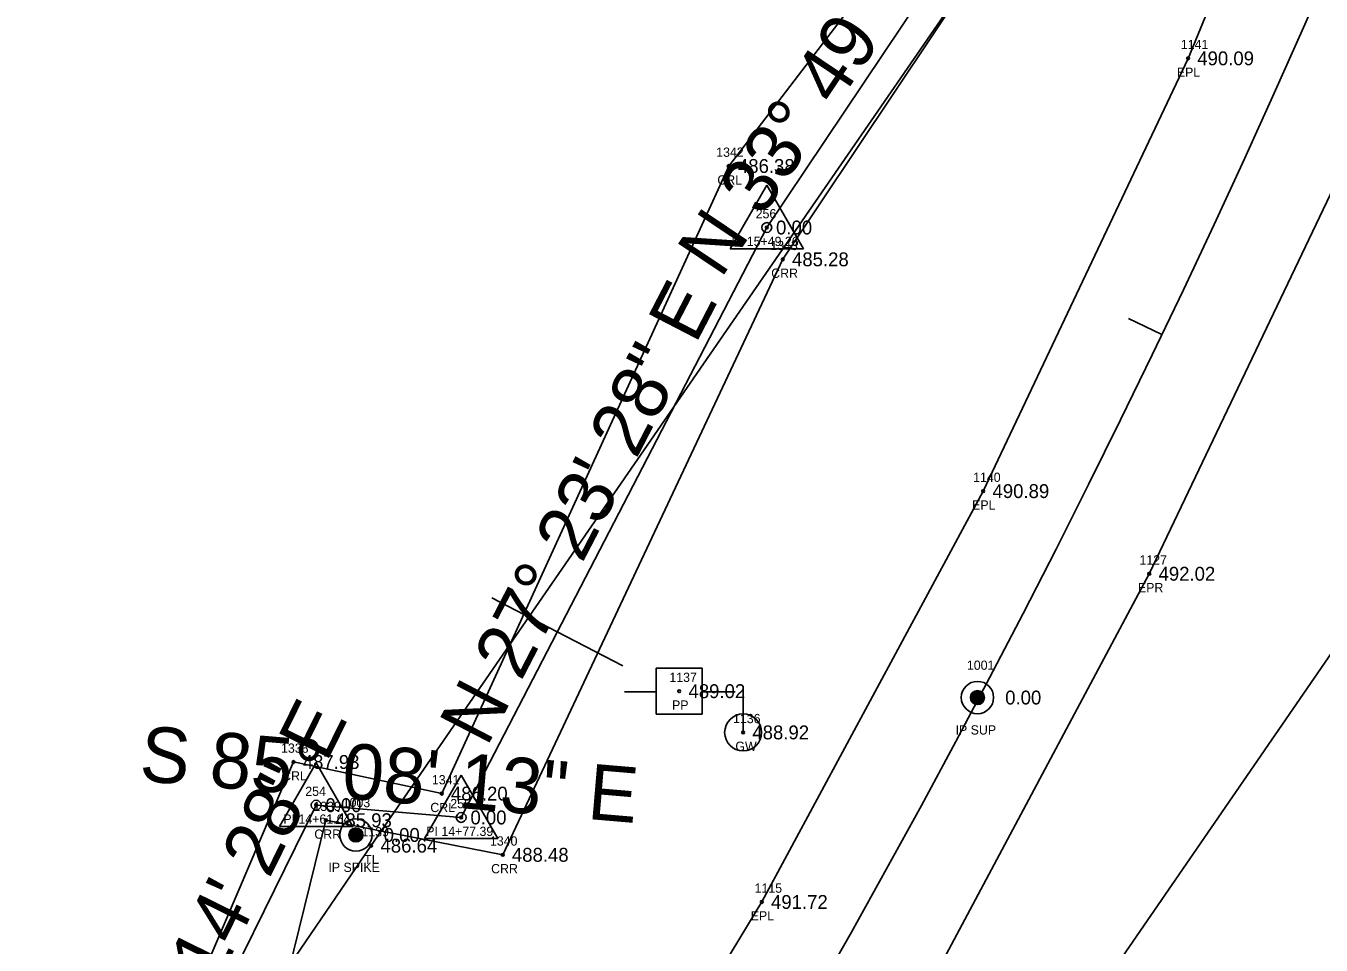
# Model space of a CAD drawing. Extents: x 1649047 to 1650429, y 896228 to 898747.
# Drawn here: x 1649708.6 to 1649848.7, y 897230.6 to 897330 of the extents above; entities that cross this region are included whole.
import ezdxf

# ---------------------------------------------------------------- set-up
doc = ezdxf.new("R2010")
doc.units = 0
for name, color, linetype in [('RD_EX_DV_Prop_txCode', 7, 'Continuous'), ('RD_EX_DV_PropPin', 7, 'Continuous'), ('RD_EX_H2O', 7, 'Continuous'), ('RD_EX_H2O_txCode', 7, 'Continuous'), ('RD_EX_Road', 7, 'Continuous'), ('RD_EX_Road_txCode', 7, 'Continuous'), ('RD_EX_TX_DV_Prop_ELEV', 7, 'Continuous'), ('RD_EX_TX_H2O_ELEV', 7, 'Continuous'), ('RD_EX_TX_Road_ELEV', 7, 'Continuous'), ('RD_EX_TX_UT_ELEV', 7, 'Continuous'), ('RD_EX_TX_VEG_ELEV', 7, 'Continuous'), ('RD_EX_UT', 7, 'Continuous'), ('RD_EX_UT_txCode', 7, 'Continuous'), ('RD_EX_VEG', 7, 'Continuous'), ('RD_EX_VEG_txCode', 7, 'Continuous'), ('RD_HC_Cl', 7, 'Continuous'), ('RD_HC_Data', 7, 'Continuous'), ('RD_HC_Data_Tic', 7, 'Continuous'), ('RD_HC_Survey_ELEV', 7, 'Continuous'), ('RD_HC_txCode', 7, 'Continuous'), ('RD_SMD_Locator', 7, 'Continuous')]:
    doc.layers.add(name, color=color, linetype=linetype)

msp = doc.modelspace()

# ---------------------------------------------------------------- linework, layer by layer
at = {"layer": 'RD_EX_DV_PropPin'}
for p, q in [((1649810.88, 897257.03), (1649810.88, 897257.77)), ((1649810.91, 897256.97), (1649810.91, 897257.82)), ((1649810.95, 897256.92), (1649810.95, 897257.87)), ((1649810.98, 897256.88), (1649810.98, 897257.91)), ((1649811.02, 897256.85), (1649811.02, 897257.95)), ((1649811.05, 897256.81), (1649811.05, 897257.98)), ((1649811.09, 897256.79), (1649811.09, 897258.01)), ((1649811.12, 897256.76), (1649811.12, 897258.03)), ((1649811.16, 897256.74), (1649811.16, 897258.05)), ((1649811.19, 897256.72), (1649811.19, 897258.07)), ((1649811.23, 897256.7), (1649811.23, 897258.09)), ((1649811.26, 897256.69), (1649811.26, 897258.1)), ((1649811.3, 897256.68), (1649811.3, 897258.12)), ((1649811.33, 897256.66), (1649811.33, 897258.13)), ((1649811.37, 897256.66), (1649811.37, 897258.14)), ((1649811.4, 897256.65), (1649811.4, 897258.14)), ((1649811.44, 897256.64), (1649811.44, 897258.15)), ((1649811.47, 897256.64), (1649811.47, 897258.15)), ((1649811.51, 897256.64), (1649811.51, 897258.16)), ((1649811.54, 897256.63), (1649811.54, 897258.16)), ((1649811.58, 897256.64), (1649811.58, 897258.16)), ((1649811.61, 897256.64), (1649811.61, 897258.15)), ((1649811.65, 897256.64), (1649811.65, 897258.15)), ((1649811.68, 897256.65), (1649811.68, 897258.14)), ((1649811.72, 897256.66), (1649811.72, 897258.14)), ((1649811.75, 897256.66), (1649811.75, 897258.13)), ((1649811.79, 897256.68), (1649811.79, 897258.12)), ((1649811.82, 897256.69), (1649811.82, 897258.1)), ((1649811.86, 897256.7), (1649811.86, 897258.09)), ((1649811.89, 897256.72), (1649811.89, 897258.07)), ((1649811.93, 897256.74), (1649811.93, 897258.05)), ((1649811.96, 897256.76), (1649811.96, 897258.03)), ((1649812, 897256.79), (1649812, 897258.01)), ((1649812.03, 897256.81), (1649812.03, 897257.98)), ((1649812.07, 897256.85), (1649812.07, 897257.95)), ((1649812.1, 897256.88), (1649812.1, 897257.91)), ((1649812.14, 897256.92), (1649812.14, 897257.87)), ((1649812.17, 897256.97), (1649812.17, 897257.82)), ((1649812.21, 897257.03), (1649812.21, 897257.77)), ((1649810.81, 897257.2), (1649810.81, 897257.59)), ((1649810.84, 897257.1), (1649810.84, 897257.69)), ((1649812.24, 897257.1), (1649812.24, 897257.69)), ((1649812.28, 897257.2), (1649812.28, 897257.59)), ((1649743.56, 897242.34), (1649743.56, 897242.73)), ((1649743.6, 897242.24), (1649743.6, 897242.84)), ((1649743.63, 897242.17), (1649743.63, 897242.91)), ((1649743.67, 897242.11), (1649743.67, 897242.96)), ((1649743.7, 897242.06), (1649743.7, 897243.01)), ((1649743.74, 897242.02), (1649743.74, 897243.05)), ((1649743.77, 897241.99), (1649743.77, 897243.09)), ((1649743.81, 897241.96), (1649743.81, 897243.12)), ((1649743.84, 897241.93), (1649743.84, 897243.15)), ((1649743.88, 897241.9), (1649743.88, 897243.17)), ((1649743.91, 897241.88), (1649743.91, 897243.19)), ((1649743.95, 897241.86), (1649743.95, 897243.21)), ((1649743.98, 897241.85), (1649743.98, 897243.23)), ((1649744.02, 897241.83), (1649744.02, 897243.25)), ((1649744.05, 897241.82), (1649744.05, 897243.26)), ((1649744.09, 897241.81), (1649744.09, 897243.27)), ((1649744.12, 897241.8), (1649744.12, 897243.28)), ((1649744.16, 897241.79), (1649744.16, 897243.29)), ((1649744.19, 897241.78), (1649744.19, 897243.29)), ((1649744.23, 897241.78), (1649744.23, 897243.3)), ((1649744.26, 897241.78), (1649744.26, 897243.3)), ((1649744.3, 897241.78), (1649744.3, 897243.3)), ((1649744.33, 897241.78), (1649744.33, 897243.3)), ((1649744.37, 897241.78), (1649744.37, 897243.3)), ((1649744.4, 897241.78), (1649744.4, 897243.29)), ((1649744.44, 897241.79), (1649744.44, 897243.29)), ((1649744.47, 897241.8), (1649744.47, 897243.28)), ((1649744.51, 897241.81), (1649744.51, 897243.27)), ((1649744.54, 897241.82), (1649744.54, 897243.26)), ((1649744.58, 897241.83), (1649744.58, 897243.25)), ((1649744.61, 897241.85), (1649744.61, 897243.23)), ((1649744.65, 897241.86), (1649744.65, 897243.21)), ((1649744.68, 897241.88), (1649744.68, 897243.19)), ((1649744.72, 897241.9), (1649744.72, 897243.17)), ((1649744.75, 897241.93), (1649744.75, 897243.15)), ((1649744.79, 897241.96), (1649744.79, 897243.12)), ((1649744.82, 897241.99), (1649744.82, 897243.09)), ((1649744.86, 897242.02), (1649744.86, 897243.05)), ((1649744.89, 897242.06), (1649744.89, 897243.01)), ((1649744.93, 897242.11), (1649744.93, 897242.96)), ((1649744.96, 897242.17), (1649744.96, 897242.91)), ((1649745, 897242.24), (1649745, 897242.84)), ((1649745.03, 897242.34), (1649745.03, 897242.73))]:
    msp.add_line(p, q, dxfattribs=at)
for centre, radius in [((1649811.54, 897257.4), 1.75), ((1649811.54, 897257.4), 0.761), ((1649744.3, 897242.54), 1.75), ((1649744.3, 897242.54), 0.761)]:
    msp.add_circle(centre, radius, dxfattribs=at)
at = {"layer": 'RD_EX_H2O'}
for points in [[(1649610.78, 897003.58), (1649606.65, 897007.8), (1649603.49, 897018.01), (1649613.66, 897065.71), (1649613.8, 897087.62), (1649648.77, 897123.4), (1649673.15, 897145.36), (1649677.84, 897170.04), (1649704.36, 897195), (1649732.98, 897211.32), (1649741.05, 897244.13), (1649760.18, 897240.39), (1649790.48, 897304.8), (1649814.66, 897340.98), (1649827.92, 897366.62), (1649835.63, 897392.05), (1649839.2, 897413.36), (1649851.88, 897417.91), (1649868.27, 897424.7)], [(1649723.06, 897216.5), (1649737.55, 897250.43), (1649753.58, 897247.01), (1649784.63, 897314.89), (1649807.13, 897344.3), (1649820.41, 897370.21), (1649823.44, 897390.83), (1649802.01, 897393.47), (1649796.5, 897387.62), (1649750.3, 897394.9), (1649722.18, 897388.11), (1649705.32, 897369.5), (1649633.55, 897374.58), (1649615.45, 897358.48), (1649595.58, 897353.05), (1649593.32, 897314.38), (1649587.49, 897281.56)]]:
    msp.add_lwpolyline(points, dxfattribs=at)
at = {"layer": 'RD_EX_Road'}
for points in [[(1649459.38, 896805.71), (1649486.55, 896839.62), (1649513.65, 896873.34), (1649538.22, 896902.56), (1649549.43, 896916.62), (1649583.1, 896957.27), (1649614.8, 896995.02), (1649647.06, 897035.69), (1649677.62, 897074.51), (1649708.33, 897114.44), (1649735.5, 897151.61), (1649762.11, 897192.19), (1649788.21, 897235.29), (1649812.17, 897279.73), (1649834.32, 897326.54), (1649852.94, 897371.82), (1649867.51, 897411.96)], [(1649474.75, 896792.65), (1649502.78, 896827.35), (1649565.2, 896903.92), (1649598.28, 896943.71), (1649629.8, 896982.26), (1649667.92, 897029.33), (1649693.13, 897061.44), (1649723.58, 897101.84), (1649752.37, 897141.09), (1649779.72, 897182.3), (1649806.12, 897225.84), (1649830.13, 897270.79), (1649852.39, 897317.43), (1649871.98, 897364.35), (1649886.55, 897406.09)]]:
    msp.add_lwpolyline(points, dxfattribs=at)
at = {"layer": 'RD_EX_UT'}
for p, q in [((1649781.77, 897260.59), (1649776.77, 897260.59)), ((1649776.77, 897260.59), (1649776.77, 897255.59)), ((1649781.77, 897255.59), (1649781.77, 897260.59)), ((1649773.34, 897258.03), (1649776.8, 897258.03)), ((1649781.7, 897258.03), (1649785.34, 897258.03)), ((1649786.19, 897253.63), (1649786.19, 897258.63)), ((1649776.77, 897255.59), (1649781.77, 897255.59))]:
    msp.add_line(p, q, dxfattribs=at)
msp.add_circle((1649786.19, 897253.63), 2, dxfattribs=at)
at = {"layer": 'RD_EX_VEG'}
for points in [[(1649617.18, 897070.52), (1649712.19, 897191.88), (1649745.96, 897241.38), (1649814.66, 897340.98), (1649833.89, 897382.46), (1649865.2, 897454.4), (1649884.45, 897522.02), (1649904.5, 897665.19), (1649923.9, 897762.32), (1649882.75, 898072.18)], [(1649692.17, 896958.45), (1649681.22, 896988.83), (1649682.34, 897025.02), (1649740.01, 897089.71), (1649819.17, 897217.64), (1649850.28, 897262.86), (1649861.15, 897270.14), (1649933.62, 897283.21)]]:
    msp.add_lwpolyline(points, dxfattribs=at)
at = {"layer": 'RD_HC_Cl'}
for p, q in [((1649788.75, 897308.24), (1649811.62, 897342.36)), ((1649755.69, 897244.43), (1649788.75, 897308.24)), ((1649725.36, 897216.06), (1649740, 897245.76)), ((1649740, 897245.76), (1649755.69, 897244.43))]:
    msp.add_line(p, q, dxfattribs=at)
msp.add_arc((1648799.37, 897792.37), 1145, 320.82481, 10.99954, dxfattribs=at)
at = {"layer": 'RD_HC_Data'}
for p, q in [((1649784.78, 897305.95), (1649788.75, 897312.83)), ((1649788.75, 897312.83), (1649792.72, 897305.95)), ((1649784.78, 897305.95), (1649792.72, 897305.95)), ((1649736.03, 897243.47), (1649740, 897250.35)), ((1649740, 897250.35), (1649743.97, 897243.47)), ((1649751.72, 897242.14), (1649755.69, 897249.02)), ((1649755.69, 897249.02), (1649759.66, 897242.14)), ((1649736.03, 897243.47), (1649743.97, 897243.47)), ((1649751.72, 897242.14), (1649759.66, 897242.14))]:
    msp.add_line(p, q, dxfattribs=at)
for centre in [(1649788.75, 897308.24), (1649740, 897245.76), (1649755.69, 897244.43)]:
    msp.add_circle(centre, 0.529, dxfattribs=at)
at = {"layer": 'RD_HC_Data_Tic'}
for p, q in [((1649831.5, 897296.66), (1649827.89, 897298.39)), ((1649766.09, 897264.5), (1649758.99, 897268.18)), ((1649766.09, 897264.5), (1649773.19, 897260.82))]:
    msp.add_line(p, q, dxfattribs=at)
at = {"layer": 'RD_SMD_Locator'}
for centre in [(1649834.32, 897326.54), (1649784.63, 897314.89), (1649788.75, 897308.24), (1649790.48, 897304.8), (1649812.17, 897279.73), (1649830.13, 897270.79), (1649779.28, 897258.09), (1649811.54, 897257.4), (1649786.19, 897253.63), (1649737.55, 897250.43), (1649753.58, 897247.01), (1649740, 897245.76), (1649741.05, 897244.13), (1649755.69, 897244.43), (1649744.3, 897242.54), (1649745.96, 897241.38), (1649760.18, 897240.39), (1649788.21, 897235.29)]:
    msp.add_circle(centre, 0.15, dxfattribs=at)

# ---------------------------------------------------------------- texts
at = {"layer": 'RD_EX_DV_Prop_txCode'}
for s, p in [('1001', (1649810.4, 897260.4)), ('IP SUP', (1649809.17, 897253.4)), ('1003', (1649742.87, 897245.54)), ('IP SPIKE', (1649741.32, 897238.54))]:
    msp.add_text(s, height=1, dxfattribs=at).set_placement(p)
at = {"layer": 'RD_EX_H2O_txCode'}
for s, p in [('1342', (1649783.28, 897315.89)), ('CRL', (1649783.4, 897312.89)), ('1343', (1649789.13, 897305.8)), ('CRR', (1649789.23, 897302.8)), ('1338', (1649736.2, 897251.43)), ('CRL', (1649736.32, 897248.43)), ('1341', (1649752.52, 897248.01)), ('1339', (1649739.7, 897245.13)), ('CRL', (1649752.35, 897245.01)), ('CRR', (1649739.8, 897242.13)), ('1340', (1649758.8, 897241.39)), ('CRR', (1649758.93, 897238.39))]:
    msp.add_text(s, height=1, dxfattribs=at).set_placement(p)
at = {"layer": 'RD_EX_Road_txCode'}
for s, p in [('1141', (1649833.54, 897327.54)), ('EPL', (1649833.11, 897324.54)), ('1140', (1649811.07, 897280.73)), ('EPL', (1649810.96, 897277.73)), ('1127', (1649829.07, 897271.79)), ('EPR', (1649828.9, 897268.79)), ('1115', (1649787.43, 897236.29)), ('EPL', (1649787.01, 897233.29))]:
    msp.add_text(s, height=1, dxfattribs=at).set_placement(p)
at = {"layer": 'RD_EX_TX_DV_Prop_ELEV'}
for p in [(1649814.54, 897256.65), (1649747.3, 897241.79)]:
    msp.add_text('0.00', height=1.5, dxfattribs=at).set_placement(p)
at = {"layer": 'RD_EX_TX_H2O_ELEV'}
for s, p in [('486.38', (1649785.63, 897314.14)), ('485.28', (1649791.48, 897304.05)), ('487.93', (1649738.55, 897249.68)), ('486.20', (1649754.58, 897246.26)), ('485.93', (1649742.05, 897243.38)), ('488.48', (1649761.18, 897239.64))]:
    msp.add_text(s, height=1.5, dxfattribs=at).set_placement(p)
at = {"layer": 'RD_EX_TX_Road_ELEV'}
for s, p in [('490.09', (1649835.32, 897325.79)), ('490.89', (1649813.17, 897278.98)), ('492.02', (1649831.13, 897270.04)), ('491.72', (1649789.21, 897234.54))]:
    msp.add_text(s, height=1.5, dxfattribs=at).set_placement(p)
at = {"layer": 'RD_EX_TX_UT_ELEV'}
msp.add_text('488.92', height=1.5, dxfattribs=at).set_placement((1649787.19, 897252.88))
at = {"layer": 'RD_EX_TX_VEG_ELEV'}
msp.add_text('486.64', height=1.5, dxfattribs=at).set_placement((1649746.96, 897240.63))
at = {"layer": 'RD_EX_UT_txCode'}
for s, p in [('1137', (1649778.21, 897259.09)), ('PP', (1649778.5, 897256.09)), ('1136', (1649785.1, 897254.63)), ('GW', (1649785.35, 897251.63))]:
    msp.add_text(s, height=1, dxfattribs=at).set_placement(p)
at = {"layer": 'RD_EX_VEG_txCode'}
for s, p in [('1139', (1649744.9, 897242.38)), ('TL', (1649745.19, 897239.38))]:
    msp.add_text(s, height=1, dxfattribs=at).set_placement(p)
at = {"layer": 'RD_HC_Data'}
for s, rotation, p in [('N 33%%d 49\' 34" E', 56.1739, (1649783.78, 897302.61)), ('N 27%%d 23\' 28" E', 62.6089, (1649758.46, 897251.95)), ('N 26%%d 14\' 28" E', 63.759, (1649719.41, 897206.26)), ('S 85%%d 08\' 13" E', 355.137, (1649720.78, 897248.4))]:
    msp.add_text(s, height=6, rotation=rotation, dxfattribs=at).set_placement(p)
at = {"layer": 'RD_HC_Survey_ELEV'}
for s, p in [('0.00', (1649789.75, 897307.49)), ('489.02', (1649780.28, 897257.34)), ('0.00', (1649741, 897245.01)), ('0.00', (1649756.69, 897243.68))]:
    msp.add_text(s, height=1.5, dxfattribs=at).set_placement(p)
at = {"layer": 'RD_HC_txCode'}
for s, p in [('256', (1649787.55, 897309.24)), ('PI 15+49.26', (1649784.95, 897306.24)), ('254', (1649738.82, 897246.76)), ('255', (1649754.51, 897245.43)), ('PI 14+61.64', (1649736.45, 897243.76)), ('PI 14+77.39', (1649751.91, 897242.43))]:
    msp.add_text(s, height=1, dxfattribs=at).set_placement(p)

doc.saveas('drawing.dxf')
